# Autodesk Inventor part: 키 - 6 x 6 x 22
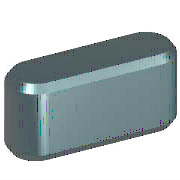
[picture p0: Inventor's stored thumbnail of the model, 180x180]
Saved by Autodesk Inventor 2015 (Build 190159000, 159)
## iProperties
IsCustomPart: 1
Created: 2012-02
Part Number: 키 - 6 x 6 x 22
Material: 강철, 연강
Description: 키 및 해당 키홈
Document SubType Name: Modeling
Standard: KS B 1311
Designer: mduedu
Standards Organization: KS
Language: ko-KR
Size Designation: 6 x 6 x 22
Categories: <MemberInstance><Categories><Category DisplayName="샤프트 부품" InternalName="7f7aeb1f-a693-4053-b835-cee3144e0d98" Mnemonic="SHFT"><Category DisplayName="키" Interna
Density: 7.86 g/cm^3
Mass: 5.79788 g
Surface Area: 5.294 cm^2
Volume: 0.737644 cm^3
Appearance: 강철
Author: mduedu
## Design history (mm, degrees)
workplane "Work Plane1"
workplane "Work Plane2"
sketch "스케치1"
  geometry: L1 (3, 3)-(19, 3); L2 (19, -3)-(3, -3); L3 (0, 9.4)-(0, -7.4) reference; L4 (-5, 0)-(30, 0) reference; L5 (22, 0)-(22, 7); A1 r 3 centre (3, 0) between (3, 3) and (3, -3); A2 r 3 centre (19, 0) between (19, -3) and (19, 3)
  constraints: 6 end point, 5 point on circle, 4 tangent, 3 point on line, 2 centre point, 1 horizontal, 1 parallel, 1 perpendicular
  dimensions: "d0" = 3 radius of A1 (= 0.5 x PB); "d13" = 3 radius of A2 (= 0.5 x PB); "d14" = 22 distance between parallel lines of L5 L3 (= NLG)
extrude "본체1" new body sketch "스케치1" taper "d3" = 0 deg; stored distance "d4" = 10
workplane "Work Plane3"
body "Solid1"
chamfer "모따기1" distance "d8" = 0.4 (= PHH); stored, may be unused: second distance "d9" = 0.4 (= PHH), angle "d15" = 45 deg
other parameters: "d1" = -3.5 (= -PNT), "d2" = 2.5 (= PH - PNT), "NLG" = 22 [user parameter; used in 3 equation terms], "PB" = 6 [user parameter; used in 2 equation terms], "PNT" = 3.5 [user parameter; used in 2 equation terms], "PH" = 6 [user parameter; used in 1 equation term], "PHH" = 0.4 [user parameter; used in 2 equation terms], "d10" = 0, "d16" = 0, "d17" = 0, "d18" = 0, "WDMIN" = 17 [user parameter], "PLB2" = 22 (= NLG) [user parameter], "WDMAX" = 22 [user parameter], "PLB1" = 22 (= NLG) [user parameter], "RR" = 0.16 [user parameter], "PUEB" = 2.8 [user parameter]
